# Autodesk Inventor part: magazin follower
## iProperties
Created: 2006-04
Part Number: magazin follower
Document SubType Name: Modeling
Designer: Калинин
Author: Калинин
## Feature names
1. Выдавливание1 [Extrusion]
2. Выдавливание2 [Extrusion]
3. Выдавливание3 [Extrusion]
4. Сопряжение1 [Fillet]
5. Сопряжение2 [Fillet]
6. Оболочка1
7. Выдавливание4 [Extrusion]
8. Сопряжение4 [Fillet]
9. Выдавливание5 [Extrusion]
10. Сопряжение5 [Fillet]
11. Выдавливание6 [Extrusion]
12. Сопряжение6 [Fillet]
